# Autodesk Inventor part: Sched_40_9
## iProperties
Shininess: 64.0
Length Units: 11272
Angle Units: 11279
Time Units: 11290
Mass Units: 11286
Length Display Precision: 3
Angle Display Precision: 2
Compacted: True
Part Number: Sched_40_9
Document SubType Name: Modeling
Created: 2005-05
Designer: John Blackburn
Manufacturer: Standard
Standards Organization: Custom
Material: Aluminum-6061
Density: 0.0
Volumn: 0.0
Area: 0.0
PropertySet Name: Model Information
Control State: 0
Master: False
Checked Out: False
Author: John Blackburn
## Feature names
1. Extrusion1
